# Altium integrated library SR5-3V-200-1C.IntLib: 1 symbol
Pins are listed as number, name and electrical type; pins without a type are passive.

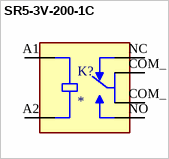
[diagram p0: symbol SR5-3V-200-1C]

## SR5-3V-200-1C
designator K?
15.6 x 10.6 x 11.8 mm, 3 V, 1 A, SPDT (1 Form C), Signal Relay; MF: CUI Devices; MP: SR5-3V-200-1C
footprint RELAY_SR5-3V-200-1C
pins: A1 COIL1, A2 COIL2, COM_1 COM1, COM_2 COM2, NC, NO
